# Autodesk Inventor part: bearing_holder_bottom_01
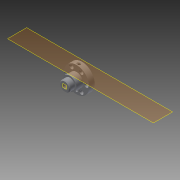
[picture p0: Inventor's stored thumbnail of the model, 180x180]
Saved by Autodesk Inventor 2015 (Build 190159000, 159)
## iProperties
Created: 2017-07
Part Number: bearing_holder_bottom_01
Material: Generic
Document SubType Name: Modeling
Designer: jonas
Density: 1 g/cm^3
Appearance: Default
Author: jonas
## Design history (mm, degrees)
workplane "Work Plane1"
sketch "Master_sketch_holder"
  geometry: L1 (0, -104)-(0, 64) reference; L2 (8.05, 13.943)-(-8.05, -13.943); L3 (6.5, 0)-(-6.5, 0); L4 (0, 0)-(-40, 0); L5 (0, 0)-(40, 0); C1 r 2.5 at (0, 0) reference; C2 r 16.6 at (0, 0); C3 r 4 at (0, -12.6); C4 r 2.2 at (0, -12.6); C5 r 2.2 at (10.912, -6.3); C6 r 4 at (10.912, -6.3); C7 r 2.2 at (10.912, 6.3); C8 r 4 at (10.912, 6.3); C9 r 2.2 at (0, 12.6); C10 r 4 at (0, 12.6); C11 r 2.2 at (-10.912, 6.3); C12 r 4 at (-10.912, 6.3); C13 r 2.2 at (-10.912, -6.3); C14 r 4 at (-10.912, -6.3); C15 r 1.23 at (-15.5, -15.5) reference; C16 r 1.23 at (15.5, -15.5) reference; C17 r 1.23 at (15.5, 15.5) reference; C18 r 1.23 at (-15.5, 15.5) reference; C19 r 2.75 at (15.5, -15.5); C20 r 8.5 at (0, 0); C21 r 1.5 at (-12, 0); C22 r 6.8 at (0, 0); C23 r 2.8 at (0, 0); A1 r 16.1 centre (0, 0) between (8.05, 13.943) and (-8.05, -13.943); A2 r 19 centre (0, 0) between (-19, 0) and (19, 0); 2 further points
  constraints: 20 centre point, 13 coincident, 10 end point, 4 point on circle, 4 point on line, 3 midpoint, 2 collinear, 1 concentric, 1 horizontal alignment, 1 line through centre, 1 tangent, 1 vertical, 30 other
  dimensions: "d20" = 0.5 radial gap between concentric circles of C2 A1; "d22" = 8 diameter of C3; "d23" = 4.4 diameter of C4; "d31" = 360 deg dimension on point (0, 0) C4.centre (derived); "d47" = 30 deg angle of L1 L2; "d68" = 13 distance of L3.start L3.end; "d115" = 40 distance of L4.start L4.end; "d116" = 180 deg angle of L4 L5; "d139" = 5.5 diameter of C19; "d140" = 38 distance of A2.start A2.end; "d141" = 2.4 radial gap between concentric circles of A2 C2; "d142" = 32.2 diameter of A1 (derived); "d153" = 2 dimension on C20; "d154" = 3 diameter of C21; "d155" = 2 dimension on C21 C20; "d156" = 0.3 dimension on C22; "d157" = 0.3 radial gap between concentric circles of C1 C23
  node "Reference5"
  node "Reference6"
  node "Reference7"
  node "Reference9"
  node "Reference10"
workplane "Work Plane2"
workplane "Work Plane3"
sketch "Sketch5"
  geometry: C1 r 16.1 at (0, 0); C2 r 2.5 at (0, 0) reference; C3 r 2.5 at (0, 0); C4 r 16.1 at (0, 0) reference; 1 further point
  constraints: 2 centre point, 2 coincident, 2 concentric
extrude "Extrusion4" new body sketch "Sketch5" distance "d73" = 1; taper "d74" = 0 deg
sketch "Sketch6"
  geometry: C1 r 16.1 at (0, 0) reference; C2 r 2.5 at (0, 0) reference; C3 r 2.5 at (0, 0); C4 r 1.5 at (0, -12) reference; 1 further point
  constraints: 1 centre point, 1 coincident, 1 concentric
extrude "Extrusion5" join sketch "Sketch6" distance "d75" = 2; taper "d76" = 0 deg
sketch "Sketch7"
  geometry: C1 r 2.2 at (-6.3, 10.912) reference; C2 r 2.2 at (6.3, 10.912) reference; C3 r 2.2 at (12.6, 0) reference; C4 r 2.2 at (6.3, -10.912) reference; C5 r 2.2 at (-6.3, -10.912) reference; C6 r 2.2 at (-12.6, 0) reference; C7 r 2.5 at (0, 0) reference; C8 r 16.1 at (0, 0) reference; C9 r 1.5 at (0, -12) reference; 2 further points
extrude "Extrusion6" join sketch "Sketch7" distance "d77" = 4; taper "d78" = 0 deg
sketch "Sketch8"
  geometry: C1 r 2.5 at (0, 0) reference; C2 r 6.5 at (0, 0); C3 r 6.5 at (0, 0) reference; 1 further point
  constraints: 1 centre point, 1 coincident, 1 concentric
extrude "Extrusion7" join sketch "Sketch8" stored distance "d79" = 2.75; taper "d80" = 0 deg
chamfer "Chamfer1" distance "d92" = 0.4; stored, may be unused: second distance "d93" = 2, angle "d94" = 45 deg
chamfer "Chamfer2" distance "d95" = 1; stored, may be unused: second distance "d96" = 2, angle "d97" = 45 deg
workplane "Work Plane6"
sketch "Sketch16"
  geometry: L1 (16.1, 7)-(-16.1, 7) reference; L2 (0, -1.4)-(0, 8.4) reference; L3 (0, 7)-(0, 0); L4 (0, 0)-(0, 3.5); L5 (0, 3.5)-(0, 7); L6 (-16.1, 0)-(16.1, 0) reference
  constraints: 6 end point, 4 midpoint, 3 point on line, 1 collinear, 1 vertical
hole "Hole2" sketch "Sketch16" at (0, 3.5) diameter "d121" = 3; stored, may be unused: countersink angle "d125" = 90 deg, drill point angle "d127" = 118 deg; dims "d122" = 6, "d123" = 4, "d124" = 2, "d126" = 18
chamfer "Chamfer4" distance "d128" = 1; stored, may be unused: second distance "d129" = 2, angle "d130" = 45 deg
sketch "Sketch19"
  geometry: C1 r 6.5 at (0, 0) reference; C2 r 8.5 at (0, 0); 1 further point
  constraints: 1 centre point
  dimensions: "d143" = 2 radial gap between concentric circles of C1 C2
extrude "Extrusion16" join sketch "Sketch19" distance "d144" = 8.5; taper "d145" = 0 deg
hole "Hole4" sketch "Master_sketch_holder" diameter "d158" = 5.4; stored, may be unused: countersink angle "d162" = 90 deg, drill point angle "d164" = 118 deg; dims "d159" = 6, "d160" = 4, "d161" = 2, "d163" = 12
body "Solid4"
other parameters: "d46" = 12
